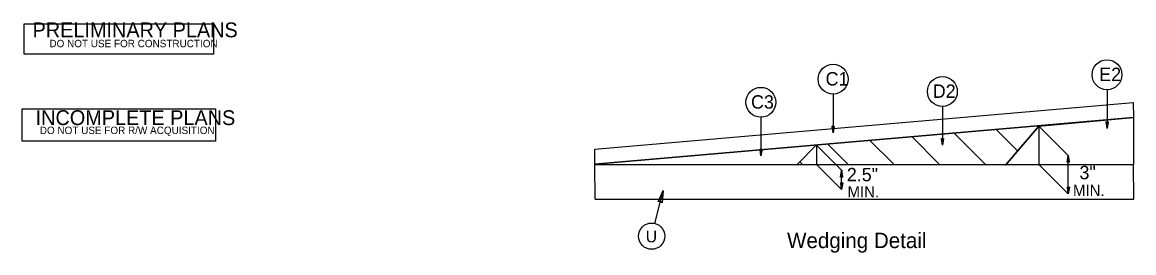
# Model space of a CAD drawing. Extents: x 193555 to 203883, y 190245 to 194645.
# Drawn here: x 200433 to 203883, y 193611 to 194326 of the extents above; entities that cross this region are included whole.
import ezdxf

# ---------------------------------------------------------------- set-up
doc = ezdxf.new("R2010")
doc.units = 0
for name, color, linetype in [('Old_Level_1', 7, 'Continuous'), ('Old_Level_11', 7, 'Continuous'), ('Old_Level_20', 7, 'Continuous'), ('Typical Detail Wedge3 CELL', 7, 'Continuous'), ('Typical ID Circle CELL', 7, 'Continuous'), ('Typical Text General CELL', 7, 'Continuous'), ('Typical Text ID Circle CELL', 7, 'Continuous')]:
    doc.layers.add(name, color=color, linetype=linetype)

msp = doc.modelspace()

# ---------------------------------------------------------------- linework, layer by layer
at = {"layer": 'Old_Level_1'}
for points in [[(200439, 194227), (200439, 194321), (201027, 194321), (201027, 194227)], [(200432.9, 194057.3), (201032.9, 194057.3), (201032.9, 193957.3), (200432.9, 193957.3)]]:
    msp.add_lwpolyline(points, close=True, dxfattribs=at)
at = {"layer": 'Old_Level_11'}
msp.add_line((202396.8, 193702.3), (202422.5, 193804.6), dxfattribs=at)
msp.add_lwpolyline([(202407, 193769.6), (202422.5, 193804.6), (202419.8, 193766.1), (202414.4, 193772.5)], close=True, dxfattribs=at)
msp.add_circle((202386.9, 193662.7), 40.8, dxfattribs=at)
at = {"layer": 'Typical Detail Wedge3 CELL'}
for p, q in [((202210.5, 193932.6), (203882, 194077.6)), ((202210.5, 193932.6), (203882, 194077.6)), ((203882, 194077.6), (203882.2, 194031.3)), ((203882, 194077.6), (203882.2, 194031.3)), ((202210.8, 193886.4), (203882.2, 194031.3)), ((203882.2, 194031.3), (202210.8, 193886.4)), ((203588.8, 194004.4), (203882.2, 194031.3)), ((203882.2, 194031.3), (203882.9, 193885.5)), ((203455.8, 193994.3), (203522.7, 193927.4)), ((203588.8, 194004.4), (203485.2, 193883.3)), ((203485.2, 193883.3), (203588.8, 194004.4)), ((203588.8, 194004.4), (203682.4, 193910.7)), ((203588.8, 194004.4), (203588.8, 193885.5)), ((203063.5, 193960.3), (203137.3, 193886.6)), ((203194.3, 193971.7), (203280.9, 193885)), ((203325, 193983), (203422.7, 193885.4)), ((202210.8, 193886.4), (202210.5, 193932.6)), ((202210.8, 193886.4), (202210.5, 193932.6)), ((202838.3, 193885.4), (202899, 193946.1)), ((202899, 193946.1), (202899, 193885.5)), ((202900.7, 193942.5), (202978.9, 193864.4)), ((202932.7, 193949), (202996.4, 193885.2)), ((202846.4, 193893.2), (202853.9, 193885.7)), ((203680, 193794.3), (203680.1, 193913.1)), ((202210.8, 193885.4), (203882.9, 193885.5)), ((202211.7, 193777.1), (202210.8, 193885.4)), ((202899, 193885.5), (202976.7, 193807.7)), ((202976.7, 193807.7), (202976.6, 193866.6)), ((203882.9, 193885.5), (203485.2, 193883.3)), ((203588.8, 193885.5), (203680, 193794.3)), ((203883.5, 193777.2), (203882.9, 193885.5)), ((202211.7, 193777.1), (203883.5, 193777.2))]:
    msp.add_line(p, q, dxfattribs=at)
for points in [[(202953.8, 194004), (202950.1, 194001.3), (202946.4, 194004), (202950.1, 193983.4), (202947.5, 194003.2), (202948.5, 194002.4), (202950.1, 193983.4), (202949.6, 194001.7), (202950.1, 194001.3), (202950.1, 193983.4), (202951.1, 194002.1), (202952.2, 194002.8), (202950.1, 193983.4), (202953.2, 194003.6), (202953.8, 194004), (202950.1, 193983.4)], [(203804.1, 194017.8), (203800.4, 194015.1), (203796.7, 194017.8), (203800.4, 193997.2), (203797.8, 194017), (203798.8, 194016.2), (203800.4, 193997.2), (203799.9, 194015.5), (203800.4, 194015.1), (203800.4, 193997.2), (203801.4, 194015.9), (203802.5, 194016.6), (203800.4, 193997.2), (203803.5, 194017.4), (203804.1, 194017.8), (203800.4, 193997.2)], [(203293, 193965.6), (203289.3, 193962.9), (203285.6, 193965.6), (203289.3, 193945), (203286.7, 193964.8), (203287.7, 193964), (203289.3, 193945), (203288.8, 193963.3), (203289.3, 193962.9), (203289.3, 193945), (203290.3, 193963.7), (203291.4, 193964.5), (203289.3, 193945), (203292.4, 193965.2), (203293, 193965.6), (203289.3, 193945)], [(202729.5, 193932.2), (202725.9, 193929.5), (202722.2, 193932.2), (202725.9, 193911.7), (202723.3, 193931.5), (202724.3, 193930.7), (202725.9, 193911.7), (202725.3, 193929.9), (202725.9, 193929.5), (202725.9, 193911.7), (202726.9, 193930.3), (202727.9, 193931.1), (202725.9, 193911.7), (202729, 193931.8), (202729.5, 193932.2), (202725.9, 193911.7)], [(203676.4, 193892.5), (203680, 193895.2), (203683.7, 193892.5), (203680.1, 193913.1), (203682.7, 193893.3), (203681.6, 193894), (203680.1, 193913.1), (203680.6, 193894.8), (203680, 193895.2), (203680.1, 193913.1), (203679.1, 193894.4), (203678, 193893.6), (203680.1, 193913.1), (203677, 193892.9), (203676.4, 193892.5), (203680.1, 193913.1)], [(202973, 193846.1), (202976.6, 193848.8), (202980.3, 193846.1), (202976.6, 193866.7), (202979.3, 193846.9), (202978.2, 193847.6), (202976.6, 193866.7), (202977.2, 193848.4), (202976.6, 193848.8), (202976.6, 193866.7), (202975.6, 193848), (202974.6, 193847.2), (202976.6, 193866.7), (202973.5, 193846.5), (202973, 193846.1), (202976.6, 193866.7)], [(202980.3, 193828.3), (202976.7, 193825.6), (202973, 193828.3), (202976.7, 193807.7), (202974.1, 193827.5), (202975.1, 193826.7), (202976.7, 193807.7), (202976.1, 193826), (202976.7, 193825.6), (202976.7, 193807.7), (202977.7, 193826.4), (202978.7, 193827.2), (202976.7, 193807.7), (202979.8, 193827.9), (202980.3, 193828.3), (202976.7, 193807.7)], [(203683.6, 193814.9), (203680, 193812.2), (203676.4, 193814.9), (203680, 193794.3), (203677.4, 193814.1), (203678.4, 193813.3), (203680, 193794.3), (203679.5, 193812.6), (203680, 193812.2), (203680, 193794.3), (203681.1, 193813), (203682.1, 193813.7), (203680, 193794.3), (203683.2, 193814.5), (203683.6, 193814.9), (203680, 193794.3)]]:
    msp.add_lwpolyline(points, dxfattribs=at)
at = {"layer": 'Typical ID Circle CELL'}
for p, q in [((202950.1, 194103.3), (202950.1, 193983.4)), ((203800.4, 194117.1), (203800.4, 193997.2)), ((203289.3, 194065), (203289.3, 193945)), ((202725.9, 194031.6), (202725.9, 193911.7))]:
    msp.add_line(p, q, dxfattribs=at)
for centre in [(203800.4, 194163.5), (202950.1, 194149.7), (203289.3, 194111.4), (202725.9, 194078)]:
    msp.add_circle(centre, 46.4, dxfattribs=at)

# ---------------------------------------------------------------- texts
at = {"layer": 'Old_Level_1'}
for s, height, p in [('PRELIMINARY PLANS', 46.08, (200465, 194279.6)), ('DO NOT USE FOR CONSTRUCTION', 23.04, (200517.4, 194248.8)), ('INCOMPLETE PLANS', 46.08, (200474.5, 194007.3)), ('DO NOT USE FOR R/W ACQUISITION', 23.04, (200487.5, 193979.5))]:
    msp.add_text(s, height=height, dxfattribs=at).set_placement(p)
at = {"layer": 'Old_Level_20'}
msp.add_text('U', height=36.5, rotation=0.4249, dxfattribs=at).set_placement((202368.7, 193643.4))
at = {"layer": 'Typical Detail Wedge3 CELL'}
for s, height, p in [('2.5"', 41.54, (202992.7, 193833)), ('3"', 41.54, (203714.9, 193839.4)), ('MIN.', 34.71, (203694.9, 193787.4)), ('MIN.', 34.71, (202995, 193782.9))]:
    msp.add_text(s, height=height, dxfattribs=at).set_placement(p)
at = {"layer": 'Typical Text General CELL'}
msp.add_text('Wedging Detail', height=47.742, dxfattribs=at).set_placement((202807.1, 193625.6))
at = {"layer": 'Typical Text ID Circle CELL'}
for s, p in [('C1', (202926.8, 194130.1)), ('E2', (203776.2, 194143.9)), ('D2', (203259.5, 194091.8)), ('C3', (202695.3, 194058.4))]:
    msp.add_text(s, height=41.54, dxfattribs=at).set_placement(p)

doc.saveas('drawing.dxf')
